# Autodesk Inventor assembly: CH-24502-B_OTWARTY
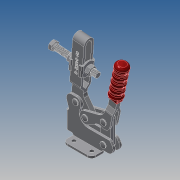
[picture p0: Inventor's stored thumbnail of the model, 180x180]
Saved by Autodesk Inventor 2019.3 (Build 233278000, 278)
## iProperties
Company: ·L?¤¤?
Created: 2010-06
Part Number: CH-24502-B_OTWARTY
Material: Ogólny
Description: STEP AP203
Document SubType Name: Assembly
Designer: CADENGINEERING4
Sending System: SolidWorks 2005179
Preprocessor: SwSTEP 2.0
Title: CH-24502-B.STEP
Author: ·L?¥Î?
Revision Number: ANY
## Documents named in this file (11)
- E:\STRONA\Horizontal toggle clamp\CH-24502-B\CH-24502-B_OTWARTY.iam
- E:\STRONA\Horizontal toggle clamp\CH-24502-B\FW120___.ipt
- E:\STRONA\Horizontal toggle clamp\CH-24502-B\CH-24502-B-06___.ipt
- E:\STRONA\Horizontal toggle clamp\CH-24502-B\CH-24502-B-05___.ipt
- E:\STRONA\Horizontal toggle clamp\CH-24502-B\101-J-06___.ipt
- E:\STRONA\Horizontal toggle clamp\CH-24502-B\CH-SA-121017___.ipt
- E:\STRONA\Horizontal toggle clamp\CH-24502-B\M12___.ipt
- E:\STRONA\Horizontal toggle clamp\CH-24502-B\CH-24502-B-02___.ipt
- E:\STRONA\Horizontal toggle clamp\CH-24502-B\CH-24502-B-01___.ipt
- E:\STRONA\Horizontal toggle clamp\CH-24502-B\CH-24502-B-03___.ipt
- E:\STRONA\Horizontal toggle clamp\CH-24502-B\CH-24502-B-04___.ipt
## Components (17 placed, 17 different names)
1. FW120_??_1 — Równoległe:1, Zestawiające:10, Zestawiające:11, Zestawiające:13
2. CH-24502-B-06_??_2 — Zestawiające:1, Zestawiające:2, Zestawiające:3
3. CH-24502-B-05_??_3 — Zestawiające:19, Zestawiające:20
4. 101-J-06_??_4 — Równoległe:3, Zestawiające:27, Zestawiające:36, Zestawiające:37
5. CH-SA-121017_??_5 — Zestawiające:5, Zestawiające:7, Równoległe:2, Zestawiające:10, Zestawiające:12, Zestawiające:14
6. FW120_??_6 — Zestawiające:4, Zestawiające:5, Zestawiające:6, Równoległe:1, Zestawiające:8, Zestawiające:9
7. CH-24502-B-05_??_7 — Zestawiające:30, Zestawiające:31
8. M12_??_8 — Zestawiające:7, Zestawiające:8, Równoległe:2
9. CH-24502-B-02_??_9 — Zestawiające:4, Zestawiające:6, Zestawiające:9, Zestawiające:11, Zestawiające:14, Zestawiające:17, Zestawiające:18, Równoległe:3, Zestawiające:27
10. CH-24502-B-05_??_10 — Zestawiające:37, Zestawiające:38
11. CH-24502-B-01_??_11 — Zestawiające:15, Zestawiające:16, Zestawiające:17, Zestawiające:18, Zestawiające:19, Zestawiające:20, Zestawiające:26, Zestawiające:28, Zestawiające:29, Zestawiające:30, Zestawiające:31, Przejściowe:1
12. CH-24502-B-05_??_12 — Zestawiające:34, Zestawiające:35
13. CH-24502-B-03_??_13 — Zestawiające:1, Zestawiające:2, Zestawiające:3, Zestawiające:32, Zestawiające:33, Zestawiające:34, Zestawiające:35, Zestawiające:36, Zestawiające:38, Przejściowe:1
14. M12_??_14 — Zestawiające:12, Zestawiające:13
15. CH-24502-B-04_??_15 — Zestawiające:23, Zestawiające:24, Zestawiające:25
16. CH-24502-B-04_??_16 — Zestawiające:23, Zestawiające:24, Zestawiające:25, Zestawiające:26, Zestawiające:28, Zestawiające:29, Zestawiające:32, Zestawiające:33
17. 101-J-06_??_17 — Zestawiające:15, Zestawiające:16
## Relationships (40: Mate 36, Flush 3, Transitional 1)
- Zestawiające:1 [Mate]: CH-24502-B-06_??_2 ↔ CH-24502-B-03_??_13
- Zestawiające:2 [Mate]: CH-24502-B-06_??_2 ↔ CH-24502-B-03_??_13
- Zestawiające:3 [Mate]: CH-24502-B-06_??_2 ↔ CH-24502-B-03_??_13
- Zestawiające:4 [Mate]: FW120_??_6 ↔ CH-24502-B-02_??_9
- Zestawiające:5 [Mate]: CH-SA-121017_??_5 ↔ FW120_??_6
- Zestawiające:6 [Mate]: FW120_??_6 ↔ CH-24502-B-02_??_9
- Równoległe:1 [Flush]: FW120_??_1 ↔ FW120_??_6
- Zestawiające:7 [Mate]: CH-SA-121017_??_5 ↔ M12_??_8
- Zestawiające:8 [Mate]: FW120_??_6 ↔ M12_??_8
- Równoległe:2 [Flush]: CH-SA-121017_??_5 ↔ M12_??_8
- Zestawiające:9 [Mate]: FW120_??_6 ↔ CH-24502-B-02_??_9
- Zestawiające:10 [Mate]: FW120_??_1 ↔ CH-SA-121017_??_5
- Zestawiające:11 [Mate]: FW120_??_1 ↔ CH-24502-B-02_??_9
- Zestawiające:12 [Mate]: CH-SA-121017_??_5 ↔ M12_??_14
- Zestawiające:13 [Mate]: FW120_??_1 ↔ M12_??_14
- Zestawiające:14 [Mate]: CH-SA-121017_??_5 ↔ CH-24502-B-02_??_9
- Zestawiające:15 [Mate]: CH-24502-B-01_??_11 ↔ 101-J-06_??_17
- Zestawiające:16 [Mate]: CH-24502-B-01_??_11 ↔ 101-J-06_??_17
- Zestawiające:17 [Mate]: CH-24502-B-02_??_9 ↔ CH-24502-B-01_??_11
- Zestawiające:18 [Mate]: CH-24502-B-02_??_9 ↔ CH-24502-B-01_??_11
- Zestawiające:19 [Mate]: CH-24502-B-05_??_3 ↔ CH-24502-B-01_??_11
- Zestawiające:20 [Mate]: CH-24502-B-05_??_3 ↔ CH-24502-B-01_??_11
- Zestawiające:23 [Mate]: CH-24502-B-04_??_15 ↔ CH-24502-B-04_??_16
- Zestawiające:24 [Mate]: CH-24502-B-04_??_15 ↔ CH-24502-B-04_??_16
- Zestawiające:25 [Mate]: CH-24502-B-04_??_15 ↔ CH-24502-B-04_??_16
- Zestawiające:26 [Mate]: CH-24502-B-01_??_11 ↔ CH-24502-B-04_??_16
- Równoległe:3 [Flush]: 101-J-06_??_4 ↔ CH-24502-B-02_??_9
- Zestawiające:27 [Mate]: 101-J-06_??_4 ↔ CH-24502-B-02_??_9
- Zestawiające:28 [Mate]: CH-24502-B-01_??_11 ↔ CH-24502-B-04_??_16
- Zestawiające:29 [Mate]: CH-24502-B-01_??_11 ↔ CH-24502-B-04_??_16
- Zestawiające:30 [Mate]: CH-24502-B-05_??_7 ↔ CH-24502-B-01_??_11
- Zestawiające:31 [Mate]: CH-24502-B-05_??_7 ↔ CH-24502-B-01_??_11
- Zestawiające:32 [Mate]: CH-24502-B-03_??_13 ↔ CH-24502-B-04_??_16
- Zestawiające:33 [Mate]: CH-24502-B-03_??_13 ↔ CH-24502-B-04_??_16
- Zestawiające:34 [Mate]: CH-24502-B-05_??_12 ↔ CH-24502-B-03_??_13
- Zestawiające:35 [Mate]: CH-24502-B-05_??_12 ↔ CH-24502-B-03_??_13
- Zestawiające:36 [Mate]: 101-J-06_??_4 ↔ CH-24502-B-03_??_13
- Zestawiające:37 [Mate]: 101-J-06_??_4 ↔ CH-24502-B-05_??_10
- Zestawiające:38 [Mate]: CH-24502-B-05_??_10 ↔ CH-24502-B-03_??_13
- Przejściowe:1 [Transitional]: CH-24502-B-01_??_11 ↔ CH-24502-B-03_??_13
